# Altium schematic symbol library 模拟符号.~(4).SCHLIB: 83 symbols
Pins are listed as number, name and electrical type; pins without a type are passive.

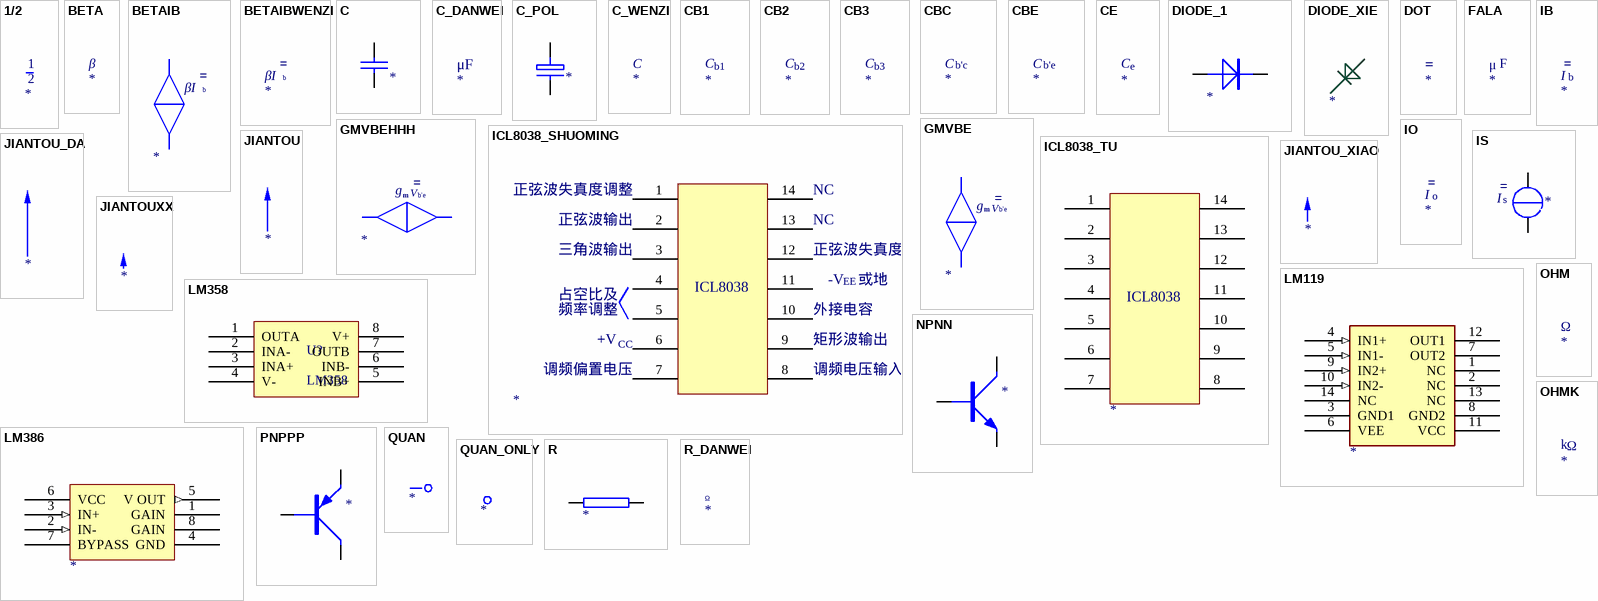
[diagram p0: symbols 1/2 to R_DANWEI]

## 1/2
designator ?

## BETA
designator ?

## BETAIB
designator ?

## BETAIBWENZI
designator ?

## C
designator ?
pins: 1, 2

## C_DANWEI
designator ?

## C_POL
designator ?
pins: 1, 2

## C_WENZI
designator ?

## CB1
designator ?

## CB2
designator ?

## CB3
designator ?

## CBC
designator ?

## CBE
designator ?

## CE
designator ?

## DIODE_1
designator ?
pins: 1 A, 2 K

## DIODE_XIE
designator ?

## DOT
designator ?

## FALA
designator ?

## GMVBE
designator ?

## GMVBEHHH
designator ?

## IB
designator ?

## ICL8038_SHUOMING
designator ?
pins: 1 74, 2 75, 3 76, 4 77, 5 78, 6 79, 7 80, 8 81, 9 82, 10 83, 11 84, 12 85, 13 86, 14 87

## ICL8038_TU
designator ?
pins: 1 74, 2 75, 3 76, 4 77, 5 78, 6 79, 7 80, 8 81, 9 82, 10 83, 11 84, 12 85, 13 86, 14 87

## IO
designator ?

## IS
designator ?
pins: 1, 2

## JIANTOU
designator ?

## JIANTOU_DA
designator ?

## JIANTOU_XIAO
designator ?

## JIANTOUXX
designator ?

## LM119
designator ?
pins: 1 NC, 2 NC, 3 GND1 (power), 4 IN1+ (in), 5 IN1- (in), 6 VEE (power), 7 OUT2 (oc), 8 GND2 (power), 9 IN2+ (in), 10 IN2- (in), 11 VCC (power), 12 OUT1 (oc), 13 NC, 14 NC

## LM358
designator U?
pins: 1 OUTA, 2 INA-, 3 INA+, 4 V- (power), 5 INB+, 6 INB-, 7 OUTB, 8 V+

## LM386
designator ?
footprint DIP08
pins: 1 GAIN, 2 IN- (in), 3 IN+ (in), 4 GND (power), 5 V OUT (out), 6 VCC, 7 BYPASS, 8 GAIN

## NPNN
designator ?
pins: 1 B, 2 C, 3 E

## OHM
designator ?

## OHMK
designator ?

## PNPPP
designator ?
pins: 1 B, 2 E, 3 C

## QUAN
designator ?

## QUAN_ONLY
designator ?

## R
designator ?
pins: 1, 2

## R_DANWEI
designator ?

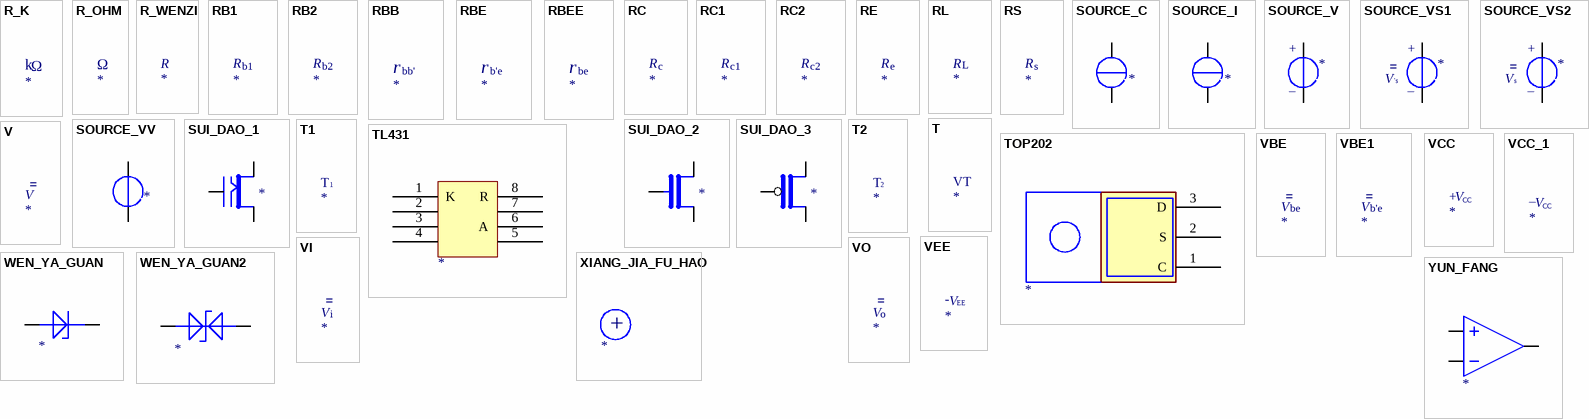
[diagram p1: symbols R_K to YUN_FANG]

## R_K
designator ?

## R_OHM
designator ?

## R_WENZI
designator ?

## RB1
designator ?

## RB2
designator ?

## RBB
designator ?

## RBE
designator ?

## RBEE
designator ?

## RC
designator ?

## RC1
designator ?

## RC2
designator ?

## RE
designator ?

## RL
designator ?

## RS
designator ?

## SOURCE_C
designator ?
pins: 1, 2

## SOURCE_I
designator ?
pins: 1, 2

## SOURCE_V
designator ?
pins: 1, 2

## SOURCE_VS1
designator ?
pins: 1, 2

## SOURCE_VS2
designator ?
pins: 1, 2

## SOURCE_VV
designator ?
pins: 1, 2

## SUI_DAO_1
designator ?
pins: 67, 68, 69

## SUI_DAO_2
designator ?
pins: 67, 68, 69

## SUI_DAO_3
designator ?
pins: 67, 68, 69

## T
designator ?

## T1
designator ?

## T2
designator ?

## TL431
designator ?
pins: 1 K, 2, 3, 4, 5, 6 A, 7, 8 R

## TOP202
designator ?
pins: 1 C, 2 S, 3 D

## V
designator ?

## VBE
designator ?

## VBE1
designator ?

## VCC
designator ?

## VCC_1
designator ?

## VEE
designator ?

## VI
designator ?

## VO
designator ?

## WEN_YA_GUAN
designator ?
pins: 1 A, 2 K

## WEN_YA_GUAN2
designator ?
pins: 1 A, 2 K

## XIANG_JIA_FU_HAO
designator ?

## YUN_FANG
designator ?
pins: 1 IN-, 2 IN+, 3 OUT

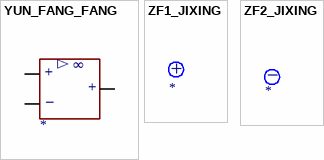
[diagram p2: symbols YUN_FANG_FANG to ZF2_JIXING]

## YUN_FANG_FANG
designator ?
pins: 42, 43, 44

## ZF1_JIXING
designator ?

## ZF2_JIXING
designator ?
